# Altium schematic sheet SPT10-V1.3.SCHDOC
size A4
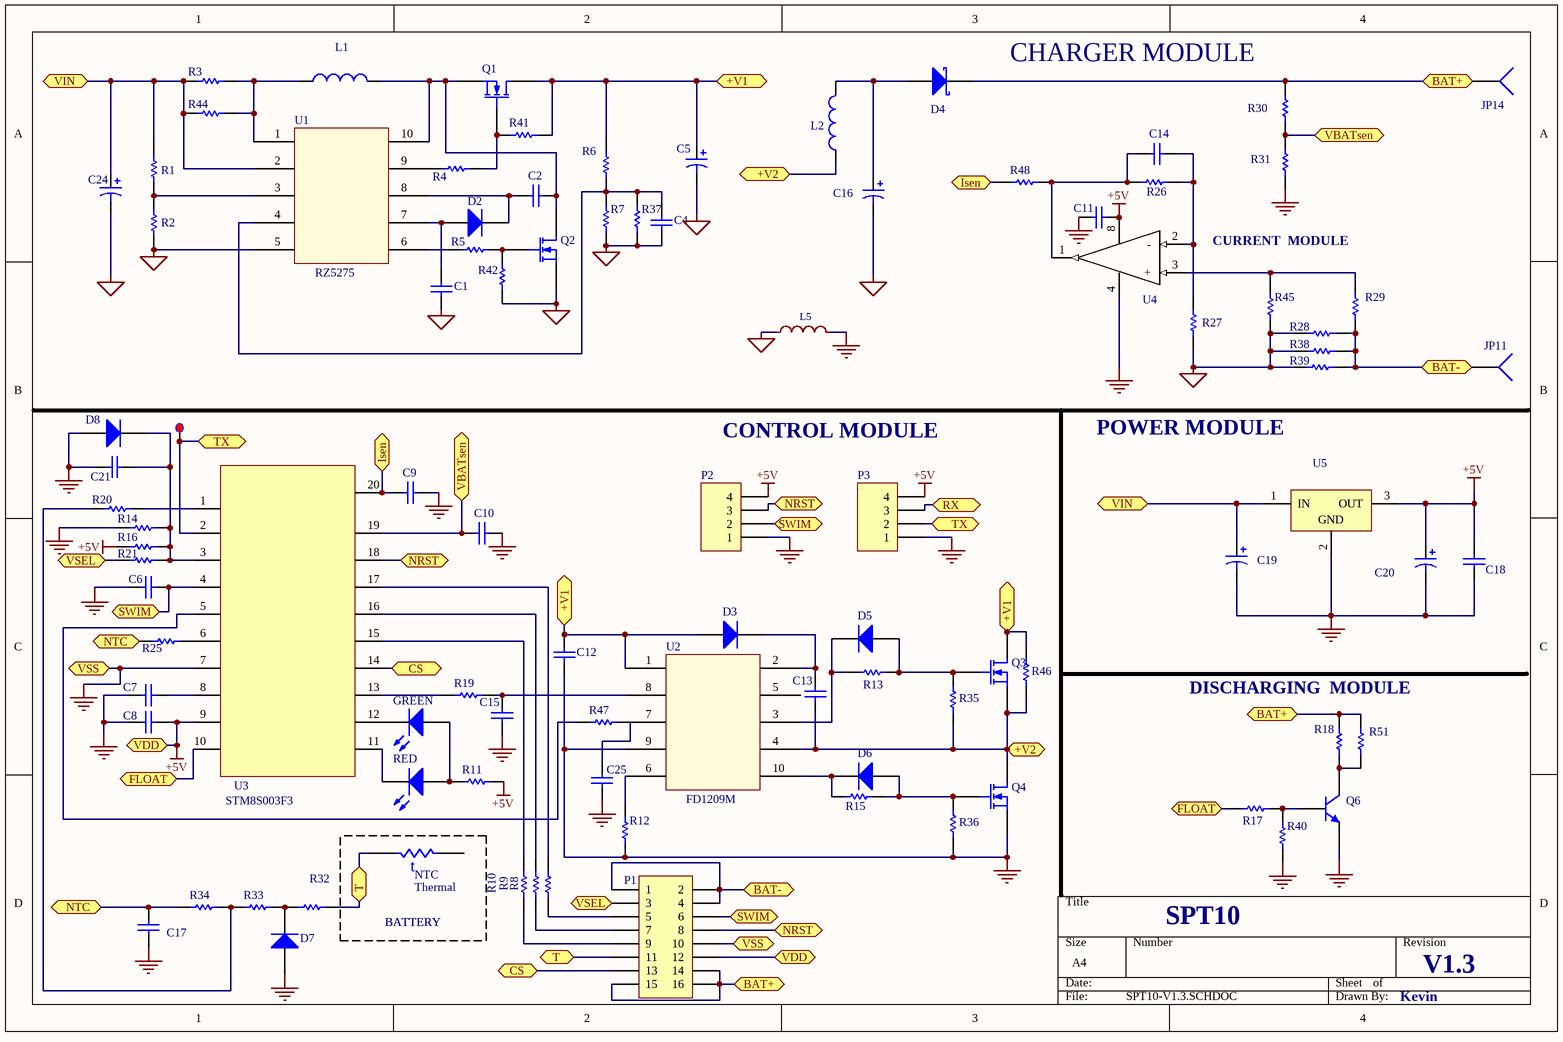
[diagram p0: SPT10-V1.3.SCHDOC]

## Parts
*  *  (value not drawn)
C1  (no value)  [1206]
C2  104  [1206]  (value not drawn)
C4  (no value)  [1206]
C5  (no value)  [10*10.5]
C6  (no value)  [1206]
C7  (no value)  [1206]
C8  (no value)  [1206]
C9  (no value)  [1206]
C10  (no value)  [1206]
C11  (no value)  [1206]
C12  (no value)  [1206]
C13  (no value)  [1206]
C14  (no value)  [1206]
C15  (no value)  [1206]
C16  (no value)  [10*10.5]
C17  (no value)  [1206]
C18  (no value)  [RAD-0.3]
C19  (no value)  [RB7.6-15]
C20  (no value)  [RB7.6-15]
C21  (no value)  [1206]
C24  (no value)  [10*10.5]
C25  (no value)  [1206]
D2  (no value)  [LL34]
D3  (no value)  [SOD-123]
D4  (no value)  [1N5822]
D5  (no value)  [SOD-123]
D6  (no value)  [SOD-123]
D7  (no value)  [SOD-123]
D8  (no value)  [SOD-123]
GREEN  (no value)  [LED-2]
JP11  Socket  [PIN1]  (value not drawn)
JP14  Socket  [PIN1]  (value not drawn)
L1  (no value)  [L(SMD)]
L2  (no value)  [L(SMD)]
L5  3.3nH  [L0805]  (value not drawn)
NTC  Thermal  [6-0805]
P1  Header 8X2  [HDR2X8]  (value not drawn)
P2  Header 4  [HDR1X4]  (value not drawn)
P3  Header 4  [HDR1X4]  (value not drawn)
Q1  (no value)  [SOP-8]
Q2  (no value)  [SOP8-P]
Q3  MOSFET-N  [SOP8-P]  (value not drawn)
Q4  MOSFET-N  [SOP8-P]  (value not drawn)
Q6  (no value)  [SOT-23]
R1  (no value)  [1206]
R2  (no value)  [1206]
R3  (no value)  [1206]
R4  (no value)  [1206]
R5  (no value)  [1206]
R6  (no value)  [1206]
R7  (no value)  [1206]
R8  (no value)  [1206]
R9  (no value)  [1206]
R10  (no value)  [1206]
R11  (no value)  [1206]
R12  (no value)  [1206]
R13  (no value)  [1206]
R14  (no value)  [1206]
R15  (no value)  [1206]
R16  (no value)  [1206]
R17  (no value)  [1206]
R18  (no value)  [1206]
R19  (no value)  [1206]
R20  (no value)  [1206]
R21  (no value)  [1206]
R25  (no value)  [1206]
R26  (no value)  [1206]
R27  (no value)  [1206]
R28  (no value)  [1206]
R29  (no value)  [1206]
R30  (no value)  [1206]
R31  (no value)  [1206]
R32  (no value)  [1206]
R33  (no value)  [1206]
R34  (no value)  [1206]
R35  (no value)  [1206]
R36  (no value)  [1206]
R37  (no value)  [1206]
R38  (no value)  [1206]
R39  (no value)  [1206]
R40  (no value)  [1206]
R41  (no value)  [1206]
R42  (no value)  [1206]
R44  (no value)  [1206]
R45  (no value)  [1206]
R46  (no value)  [1206]
R47  (no value)  [1206]
R48  (no value)  [1206]
R51  (no value)  [1206]
RED  (no value)  [LED-2]
U1  RZ5275  [MS10]
U2  FD1209M  [MS10]
U3  STM8S003F3  [SSOP-20]
U4  (no value)  [SOP-8]
U5  (no value)  [T03B]

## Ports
+V1, +V2, BAT+, BAT-, CS, FLOAT, Isen, NRST, NTC, RX, SWIM, T, TX, VBATsen, VDD, VIN, VSEL, VSS

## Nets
+5V: C8.1 C11.1 C18.2 C20.1 P1.12 P2.4 P3.4 R11.2 R16.1 U3.9(VDD) U4.8 U5.3(OUT) ; port VDD
GND: C1.2 C4.2 C5.2 C6.2 C7.2 C8.2 C9.2 C10.1 C11.2 C12.2 C15.2 C16.2 C17.1 C18.1 C19.2 C20.2 C21.1 C24.2 C25.2 D7.1(A) D8.1(A) L5.1 L5.2 P1.10 P2.1 P3.1 Q2.3(S) Q4.3(S) Q6.3(E) R2.1 R7.2 R12.1 R14.1 R27.2 R28.1 R31.2 R36.1 R37.2 R38.1 R39.1 R40.1 R42.1 R45.1 U1.5(GND) U2.9(COM) U3.7(VSS) U4.4 U5.2(GND) ; port VSS
+V1: C5.1 C12.1 D3.1(A) Q1.3(D) Q3.1(D) R6.1 R41.2 R46.2 U2.1(VCC) ; port +V1
+V2: C13.2 L2.1 Q3.3(S) Q4.1(D) R35.1 R46.1 U2.4(VS) ; port +V2
BAT+: D4.1(K) JP14.1 P1.14 P1.15 P1.16 R18.1 R30.1 R51.1 ; port BAT+
BAT-: JP11.1 P1.1 P1.2 P1.4 R28.2 R29.2 R38.2 R39.2 ; port BAT-
CS: P1.13 U3.14(T_TERMINAL) ; port CS
FLOAT: R17.1 U3.10(FLOAT) ; port FLOAT
Isen: C9.1 R48.1 U3.20(CURRENT_SENSE) ; port Isen
NRST: P1.8 P2.3 U3.18(PD1/NRST) ; port NRST
NTC: C17.2 R25.2 R34.2 ; port NTC
RX: P3.3 ; port RX
SWIM: C6.1 P1.6 P2.2 U3.4(SWIM) ; port SWIM
T: NTC.1 P1.11 R32.1 ; port T
TX: *.11 P3.2 U3.2(PD5/TX) ; port TX
VBATsen: C10.2 R30.2 R31.1 U3.19(VOLT_SENSE) ; port VBATsen
VIN: C19.1 C24.1 R1.2 R3.1 R44.1 U1.2(VCC) U5.1(IN) ; port VIN
VSEL: P1.3 R21.2 ; port VSEL
NetC1_1: C1.1 D2.1(A) U1.7(VREF)
NetC2_1: C2.1 L1.2 Q1.1(S) Q2.1(D) U1.10(O_I)
NetC2_2: C2.2 D2.2(K) U1.8(O_O)
NetC4_1: C4.1 R6.2 R7.1 R37.1 U1.4(VRC)
NetC7_1: C7.1 U3.8(VCAP)
NetC13_1: C13.1 D3.2(K) U2.2(VB)
NetC14_1: C14.1 R26.2 R27.1 U4.2(-)
NetC14_2: C14.2 R26.1 R48.2 U4.1
NetC15_1: C15.1 R19.1 U2.8(IN)
NetC16_1: C16.1 D4.3(A) L2.2
NetC21_2: C21.2 D8.2(K) R14.2 R16.2 R21.1 U3.3(PD6/RX)
NetC25_1: C25.1 R47.1
NetD5_1: D5.1(A) Q3.2(G) R13.2 R35.2
NetD5_2: D5.2(K) R13.1 U2.3(HO)
NetD6_1: D6.1(A) Q4.2(G) R15.2 R36.2
NetD6_2: D6.2(K) R15.1 U2.10(LO)
NetD7_2: D7.2(K) R32.2 R33.2
NetGREEN_1: GREEN.1(A) R11.1 RED.1(A)
NetGREEN_2: GREEN.2(K) U3.12(PB4)
NetL1_1: L1.1 R3.2 R44.2 U1.1(SEN)
NetP1_5: P1.5 R8.2
NetP1_7: P1.7 R9.1
NetP1_9: P1.9 R10.1
NetQ1_2: Q1.2(G) R4.1 R41.1
NetQ2_2: Q2.2(G) R5.1 R42.2
NetQ6_1: Q6.1(C) R18.2 R51.2
NetQ6_2: Q6.2(B) R17.2 R40.2
NetR1_1: R1.1 R2.2 U1.3(EN)
NetR4_2: R4.2 U1.9(PH)
NetR5_2: R5.2 U1.6(PL)
NetR8_1: R8.1 U3.17(SPI_MISO)
NetR9_2: R9.2 U3.16(SPI_MOSI)
NetR10_2: R10.2 U3.15(SPI_SCK)
NetR12_2: R12.2 U2.6(RDT)
NetR19_2: R19.2 U3.13(PWM)
NetR20_1: R20.1 R33.1 R34.1
NetR20_2: R20.2 U3.1(NTC_CONTROL)
NetR25_1: R25.1 U3.6(PA2)
NetR29_1: R29.1 R45.2 U4.3(+)
NetR47_2: R47.2 U3.5(GD_ENABLE)
NetRED_2: RED.2(K) U3.11(PB5)

Not connected (* = marked no-connect by the designer): NTC 2; U2 5(NC) 7(EN)

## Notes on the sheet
- CHARGER MODULE
- CURRENT  MODULE
- CONTROL MODULE
- POWER MODULE
- DISCHARGING  MODULE
- BATTERY
- SPT10
- V1.3
- Kevin

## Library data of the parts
* = PAD
C1 C2 C4 C6-C15 C17 C18 C21 C25 = Cap: Capacitor
C5 C16 C19 C20 C24 = Cap Pol1: Polarized Capacitor (Radial)
D2 D3 D5-D8 = Diode 1N914: High Conductance Fast Diode
D4 = Diode 10TQ040: Schottky Rectifier; Note: Terminal 2 is the TAB and is electrically connected to the cathode
GREEN RED = LED0: Typical INFRARED GaAs LED
L1 L2 = Inductor: Code_IEC: 1005; Value: 10mH
L5 = 3.3nH: BOM_Manufacturer: Shenzhen Zhenhua Fu Elec; BOM_Manufacturer Part: CH2012H3N3S(f); nameAlias: Inductance; Contributor: LCSC
NTC = Res Thermal: Thermistor
P1 = Header 8X2: Header, 8-Pin, Dual row
P2 P3 = Header 4: Header, 4-Pin
Q1-Q4 = MOSFET-N: N-Channel MOSFET; PackageDocument: 1995/1996
Q6 = NPN: NPN Bipolar Transistor
R1-R21 R25-R42 R44-R48 R51 = Res1: Resistor; Value: 1K
U1 U2 = FD2204M
U3 = S3C9454
U4 = LMV321
U5 = LM7805CT: Series 3-Terminal Positive Regulator; Note: Tab is connected to GND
